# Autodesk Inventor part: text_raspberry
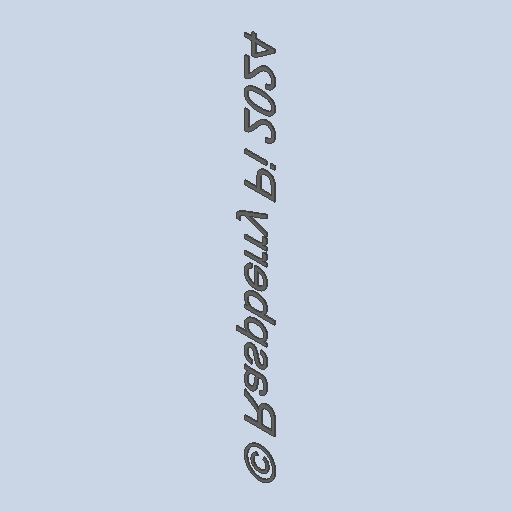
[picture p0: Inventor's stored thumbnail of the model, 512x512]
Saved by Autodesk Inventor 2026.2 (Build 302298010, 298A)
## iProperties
Created: 2026-10
Part Number: text_raspberry
Material: Générique
Document SubType Name: Modeling
Designer: mel
Density: 1 g/cm^3
Appearance: Par défaut
Author: mel
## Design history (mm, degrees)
feature "Base1"
feature "Base2"
feature "Base3"
feature "Base4"
feature "Base5"
feature "Base6"
feature "Base7"
feature "Base8"
feature "Base9"
feature "Base10"
feature "Base11"
feature "Base12"
feature "Base13"
feature "Base14"
feature "Base15"
feature "Base16"
feature "Base17"
feature "Base18"
node "Solide1"
node "Solide2"
node "Solide3"
node "Solide4"
node "Solide5"
node "Solide6"
node "Solide7"
node "Solide8"
node "Solide9"
node "Solide10"
node "Solide11"
node "Solide12"
node "Solide13"
node "Solide14"
node "Solide15"
node "Solide16"
node "Solide17"
node "Solide18"
